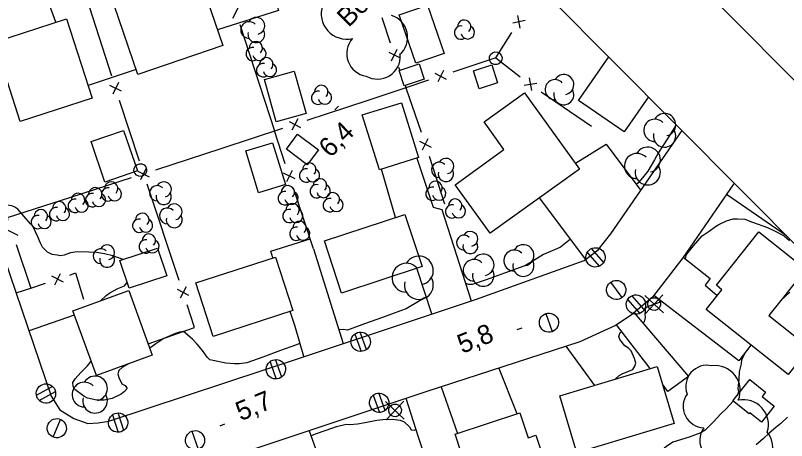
# Model space of a CAD drawing. Extents: x 381879 to 384696, y 5564785 to 5567594.
# Drawn here: x 383956.9 to 384077.4, y 5566512.9 to 5566579.5 of the extents above; entities that cross this region are included whole.
import ezdxf

# ---------------------------------------------------------------- set-up
doc = ezdxf.new("R2010")
doc.units = 0
for name, color, linetype in [('Niveau 19', 7, 'Continuous'), ('Niveau 2', 7, 'Continuous'), ('Niveau 21', 7, 'Continuous'), ('Niveau 3', 7, 'Continuous'), ('Niveau 31', 7, 'Continuous'), ('Niveau 36', 7, 'Continuous'), ('Niveau 37', 7, 'Continuous'), ('Niveau 44', 7, 'Continuous'), ('Niveau 60', 7, 'Continuous')]:
    doc.layers.add(name, color=color, linetype=linetype)

msp = doc.modelspace()

# ---------------------------------------------------------------- linework, layer by layer
at = {"layer": 'Niveau 19'}
for points in [[(383963.19, 5566578.39), (383960.58, 5566585.59)], [(383997.79, 5566580.76), (383997.95, 5566580.25), (383988.45, 5566577.19)], [(383975.72, 5566571.01), (383968.22, 5566568.49)], [(384044.35, 5566556.32), (384049.17, 5566559.34), (384054.58, 5566552.06)], [(384019.57, 5566557.12), (384022.16, 5566549.45), (384023.5, 5566549.11), (384028.1, 5566534.81)], [(384016.26, 5566547.86), (384014.04, 5566555.4)], [(384045.97, 5566541.3), (384038.75, 5566550.93)], [(384077.33, 5566544.99), (384067.96, 5566551.43)], [(383997.09, 5566541.53), (383996.76, 5566542.57), (384002.92, 5566544.51)], [(384003.44, 5566542.93), (384006.66, 5566532.61), (384008.06, 5566528.12)], [(384061.2, 5566541.62), (384065.42, 5566538.28), (384064.66, 5566537.26), (384066.52, 5566535.63)], [(384021.92, 5566532.75), (384019.6, 5566539.91)], [(383956.96, 5566536.05), (383959.41, 5566536.83)], [(384071.78, 5566527.89), (384069.87, 5566525.42), (384056.59, 5566535.63)], [(383966.07, 5566532.59), (383958.99, 5566530.11)], [(384001.95, 5566526.08), (384000.55, 5566530.77), (383999.78, 5566533.15)], [(384053.55, 5566532.95), (384062.05, 5566522.98), (384058.82, 5566520.64), (384057.95, 5566521.77)], [(384056.06, 5566524.21), (384050.78, 5566531.05)], [(384042.88, 5566527.72), (384047.37, 5566521.59)], [(384035.27, 5566517.14), (384032.41, 5566524.31)], [(384023.4, 5566521.37), (384025.96, 5566514.07)], [(384027.82, 5566507.07), (384022.54, 5566505.35), (384019.85, 5566513.5), (384017.91, 5566519.55)], [(384002.75, 5566514.47), (384005.29, 5566507.33)]]:
    msp.add_lwpolyline(points, dxfattribs=at)
at = {"layer": 'Niveau 2'}
for points in [[(383962.63, 5566542.07), (383961.89, 5566542.44), (383961.08, 5566543.22), (383960.76, 5566543.81), (383960.38, 5566544.84), (383959.62, 5566546.4), (383959.24, 5566546.86), (383957.24, 5566549.15), (383956.79, 5566549.45), (383956.29, 5566549.65), (383955.29, 5566549.82), (383953.68, 5566550.21), (383953.28, 5566550.56), (383953.09, 5566551.07), (383952.61, 5566551.98), (383952.14, 5566553.17), (383951.3, 5566555.46), (383950.23, 5566558.39), (383949.32, 5566560.95), (383948.38, 5566563.55), (383947.3, 5566565.69), (383946.95, 5566565.68)], [(384060.11, 5566562.35), (384058.69, 5566560.11), (384057.33, 5566557.99), (384056.72, 5566556.86), (384055.68, 5566555.1), (384054.87, 5566554.04), (384054.13, 5566553.21), (384053.87, 5566553.02)], [(384061.57, 5566541.33), (384061.65, 5566541.97), (384062, 5566542.35), (384062.79, 5566543.4), (384064.16, 5566544.96), (384065.28, 5566545.73), (384066.25, 5566546.45), (384066.78, 5566546.75), (384067.99, 5566547.3), (384069, 5566547.62), (384069.69, 5566547.66), (384070.81, 5566547.56), (384072.01, 5566547.14), (384074.38, 5566546.28), (384075.36, 5566545.81), (384076.97, 5566544.97), (384077.82, 5566544.26)], [(384043.61, 5566544.44), (384042.03, 5566543.19), (384041.45, 5566542.96), (384039.37, 5566542.07), (384038.29, 5566541.36), (384036.55, 5566540.34), (384035.71, 5566540.04), (384033.3, 5566539.16), (384030.41, 5566538.09), (384028.23, 5566537.36), (384027.68, 5566537.35), (384027.22, 5566537.53)], [(383973.71, 5566541.29), (383972.1, 5566541.83), (383970.8, 5566542.17), (383969.55, 5566542.35), (383968.35, 5566542.42), (383966.54, 5566542.47), (383965.47, 5566542.31), (383964.46, 5566541.94), (383963.93, 5566541.86), (383963.39, 5566541.94), (383962.63, 5566542.07)], [(383970.15, 5566534.8), (383971.04, 5566535.66), (383971.62, 5566536.06), (383972.89, 5566536.73), (383973.91, 5566537.15), (383974.34, 5566537.66)], [(384077.87, 5566536.16), (384076.41, 5566534.81)], [(384021.06, 5566535.42), (384020.7, 5566535.25), (384020.12, 5566534.85), (384017.93, 5566533.57), (384017.03, 5566533.24), (384014.21, 5566532.21), (384011.41, 5566531.19), (384008.73, 5566530.24), (384008.12, 5566530.34), (384007.4, 5566530.25)], [(384054.86, 5566531.41), (384055.18, 5566531.55), (384055.32, 5566532.21), (384055.26, 5566532.74), (384055.39, 5566533.79), (384055.95, 5566534.02)], [(384055.95, 5566534.02), (384057.81, 5566534.7)], [(383989.2, 5566525.18), (383987.25, 5566525.57), (383986.85, 5566526.02), (383986.1, 5566527.05), (383985.27, 5566528.02), (383984.54, 5566528.8), (383983.13, 5566529.99), (383982.51, 5566529.93), (383981.86, 5566529.69), (383980.07, 5566528.92), (383978.81, 5566528.07), (383977.85, 5566527.4)], [(384050.55, 5566522.55), (384051.18, 5566523.13), (384051.69, 5566523.38), (384053.33, 5566524.08), (384053.64, 5566524.58), (384053.82, 5566525.07), (384053.58, 5566525.79), (384053.07, 5566527.01), (384052.68, 5566527.38), (384052.06, 5566527.75), (384051.31, 5566528.75), (384051.15, 5566529.23), (384051.34, 5566529.83), (384051.6, 5566529.99)], [(384001.33, 5566528.15), (384000.65, 5566527.89), (383998.28, 5566527.03), (383995.5, 5566526.02), (383993.01, 5566525.13), (383991.82, 5566524.94), (383991.1, 5566524.95), (383989.73, 5566525.07), (383989.2, 5566525.18)], [(384070.93, 5566526.79), (384070.32, 5566525.58), (384070.24, 5566524.98), (384069.96, 5566523.69), (384069.91, 5566522.5), (384069.76, 5566521.1), (384069.83, 5566520.6), (384069.7, 5566520.07)], [(383974.51, 5566524.93), (383973.57, 5566524.38), (383973.02, 5566523.92), (383972.85, 5566523.37), (383973.05, 5566522.83), (383973.51, 5566521.8), (383974.04, 5566521.59), (383974.31, 5566521.12), (383973.92, 5566520.61), (383973.41, 5566520.21), (383971.99, 5566519.55), (383970.71, 5566519.27), (383969.58, 5566519.29), (383968.12, 5566519.59), (383967.57, 5566519.9), (383966.13, 5566520.93), (383965.9, 5566521.42), (383965.86, 5566522.06), (383966.19, 5566522.63), (383967.07, 5566523.61), (383968.14, 5566524.62), (383968.69, 5566525.39)], [(383988.02, 5566525.55), (383988.02, 5566525.55)], [(384069, 5566519.14), (384067.91, 5566517.92), (384067.01, 5566517.08), (384065.94, 5566515.9), (384064.66, 5566514.58), (384063.97, 5566514.18), (384062.95, 5566513.79), (384062.16, 5566513.5)], [(384003.03, 5566513.69), (384003.75, 5566513.99), (384005.4, 5566514.6), (384007.04, 5566515.13), (384008.54, 5566515.5), (384009.1, 5566515.49), (384010.32, 5566515.58), (384011.49, 5566515.77), (384013.35, 5566516.15), (384014.29, 5566516.24), (384015.77, 5566516.28), (384016.97, 5566516.13), (384017.58, 5566515.86), (384018.43, 5566515.1), (384018.68, 5566514.64), (384019.18, 5566514.57), (384019.47, 5566514.68)], [(384077.48, 5566516.59), (384076.46, 5566515.6), (384075.69, 5566515.02), (384074.64, 5566514.13), (384073.74, 5566513.25), (384072.59, 5566512.26)], [(384062.16, 5566513.5), (384059.6, 5566512.68), (384058.57, 5566512.01), (384058.21, 5566511.74)]]:
    msp.add_lwpolyline(points, dxfattribs=at)
at = {"layer": 'Niveau 21'}
for points in [[(383944.6, 5566579.59), (383944.19, 5566578.25), (383943.93, 5566576.52), (383944.16, 5566574.79), (383944.55, 5566572.83), (383954.14, 5566544.31), (383962.47, 5566519.9), (383963.82, 5566517.78), (383965.98, 5566516.39), (383968.16, 5566515.63), (383969.77, 5566515.71), (383971.47, 5566516.01), (384002.02, 5566526.1), (384028.76, 5566535.03), (384045.72, 5566541.11), (384047.93, 5566542.77), (384049.91, 5566545.28), (384061.02, 5566561.43)], [(384069.18, 5566553.2), (384061.14, 5566541.54), (384056.39, 5566535.36), (384053.09, 5566532.56), (384050.62, 5566530.94), (384045.04, 5566528.42), (384021.16, 5566520.64), (383993.82, 5566511.48), (383978.28, 5566506.25), (383975.83, 5566505.42), (383973.59, 5566504.86), (383971.33, 5566504.57), (383968.63, 5566504.67), (383966.03, 5566504.98), (383964.02, 5566505.65), (383961.77, 5566506.45), (383959.56, 5566507.5), (383957.25, 5566509.06), (383955.03, 5566511.77)]]:
    msp.add_lwpolyline(points, dxfattribs=at)
at = {"layer": 'Niveau 3'}
for p, q in [((384006.78, 5566564.69), (384007.35, 5566565.26)), ((384035.28, 5566530.33), (384036.03, 5566530.61)), ((383988.84, 5566515.25), (383989.59, 5566515.55))]:
    msp.add_line(p, q, dxfattribs=at)
at = {"layer": 'Niveau 31'}
for points in [[(383972.3, 5566581.06), (383985.59, 5566585.6), (383989.28, 5566574.77), (383975.99, 5566570.23)], [(384021.27, 5566581.07), (384023.87, 5566573.5), (384019.45, 5566571.98), (384016.85, 5566579.55)], [(383953.59, 5566575.29), (383964.85, 5566578.93), (383968.86, 5566566.52), (383957.59, 5566562.88)], [(384016.81, 5566570.83), (384019.95, 5566571.86), (384020.73, 5566569.47), (384017.59, 5566568.44)], [(384028.42, 5566570.8), (384031.29, 5566571.73), (384032.21, 5566568.9), (384029.34, 5566567.97)], [(384000.43, 5566570.74), (384002.27, 5566564.11), (383997.61, 5566562.82), (383995.77, 5566569.45)], [(384045, 5566555.42), (384031.03, 5566545.38), (384025.56, 5566552.98), (384033.2, 5566558.47), (384030.1, 5566562.79), (384036.43, 5566567.34)], [(384017.19, 5566565.8), (384019.87, 5566557.21), (384013.73, 5566555.3), (384011.05, 5566563.89)], [(383973.75, 5566561.48), (383975.93, 5566555.12), (383970.86, 5566553.38), (383968.68, 5566559.74)], [(384000.96, 5566560.87), (384004.23, 5566558.41), (384002.47, 5566556.07), (383999.2, 5566558.53)], [(383994.87, 5566551.73), (383992.86, 5566558.26), (383997.03, 5566559.54), (383999.04, 5566553.01)], [(384005.14, 5566544.17), (384017.7, 5566548.34), (384020.41, 5566540.18), (384007.84, 5566536.01)], [(384066.39, 5566537.24), (384073.01, 5566545.6), (384080.35, 5566539.78), (384074.58, 5566532.5), (384080.92, 5566527.48), (384077.6, 5566523.28), (384064.78, 5566533.44), (384067.25, 5566536.55)], [(383973.2, 5566541.12), (383979.09, 5566543.05), (383980.51, 5566538.74), (383974.62, 5566536.81)], [(384000.21, 5566533.29), (383987.76, 5566529.24), (383985.03, 5566537.61), (383997.48, 5566541.66)], [(383974.57, 5566536.41), (383978.25, 5566526.29), (383969.52, 5566523.12), (383965.84, 5566533.23)], [(384041.91, 5566519.94), (384057.11, 5566524.53), (384059.81, 5566515.63), (384044.6, 5566511.03)], [(384068.97, 5566519.17), (384071.63, 5566522.48), (384074.08, 5566520.5), (384073.55, 5566519.84), (384075.43, 5566518.32), (384073.44, 5566515.85), (384071.64, 5566517.31), (384071.5, 5566517.12)], [(384038.53, 5566508.72), (384028.38, 5566505.37), (384025.55, 5566513.93), (384035.7, 5566517.28), (384036.99, 5566513.38), (384038.17, 5566513.78), (384039.46, 5566509.87), (384038.26, 5566509.46)]]:
    msp.add_lwpolyline(points, close=True, dxfattribs=at)
msp.add_lwpolyline([(384055.78, 5566566.71), (384051.98, 5566561.23), (384044.87, 5566566.17), (384049.58, 5566572.96)], dxfattribs=at)
at = {"layer": 'Niveau 36'}
for p, q in [((384046.2, 5566542.39), (384048.1, 5566540.2)), ((384048.78, 5566540.81), (384046.88, 5566543)), ((384049.83, 5566537.73), (384051.61, 5566535.31)), ((384052.52, 5566535.02), (384054.44, 5566532.84)), ((384055.12, 5566533.46), (384053.2, 5566535.64)), ((384055.19, 5566535.66), (384058.11, 5566532.94)), ((384055.29, 5566532.84), (384058.01, 5566535.76)), ((384039.72, 5566532.81), (384040.74, 5566529.99)), ((384009.89, 5566529.6), (384010.87, 5566526.87)), ((384011.73, 5566527.2), (384010.75, 5566529.93)), ((383998.47, 5566522.89), (383997.51, 5566525.62)), ((383996.65, 5566525.29), (383997.61, 5566522.56)), ((383962.66, 5566521.41), (383960.13, 5566520)), ((383960.6, 5566519.21), (383963.13, 5566520.62)), ((384012.77, 5566520.06), (384013.77, 5566517.34)), ((384014.63, 5566517.68), (384013.63, 5566520.4)), ((384014.71, 5566519.04), (384017.63, 5566516.32)), ((384014.81, 5566516.22), (384017.53, 5566519.14)), ((383972.04, 5566516.98), (383972.91, 5566514.22)), ((383973.78, 5566514.52), (383972.91, 5566517.28)), ((383962.74, 5566513.49), (383963.92, 5566516.25)), ((383984.43, 5566514.43), (383985.43, 5566511.61))]:
    msp.add_line(p, q, dxfattribs=at)
for centre, major_axis in [((384031.92, 5566572.75), (0.799, -0.602)), ((383976.37, 5566555.27), (0.799, -0.602)), ((384047.49, 5566541.61), (-1.21, 0.91)), ((384050.73, 5566536.51), (1.2, -0.9)), ((384053.82, 5566534.23), (1.21, -0.91)), ((384056.66, 5566534.3), (0.799, -0.602)), ((384040.23, 5566531.39), (1.2, -0.9)), ((384010.81, 5566528.41), (-1.21, 0.91)), ((383997.56, 5566524.1), (-1.21, 0.91)), ((383961.64, 5566520.31), (-1.21, 0.91)), ((384013.7, 5566518.86), (1.21, -0.91)), ((384016.18, 5566517.68), (0.799, -0.602)), ((383972.91, 5566515.76), (-1.21, 0.91)), ((383963.33, 5566514.88), (-1.2, 0.9)), ((383984.93, 5566513.01), (1.2, -0.9))]:
    msp.add_ellipse(centre, major_axis=major_axis, ratio=0.999875, dxfattribs=at)
at = {"layer": 'Niveau 37'}
for p, q in [((383971.92, 5566569.96), (383967.05, 5566585.07)), ((383990.85, 5566579.05), (383991.76, 5566580.84)), ((384014.13, 5566579.11), (384015.44, 5566575.16)), ((384036.53, 5566578.65), (384034.56, 5566578.23)), ((384035.75, 5566577.46), (384035.34, 5566579.42)), ((383991.93, 5566578.04), (383997.33, 5566561.4)), ((384031.92, 5566572.82), (384034.45, 5566576.77)), ((384015.19, 5566573.71), (384016.99, 5566572.82)), ((384015.65, 5566572.36), (384016.53, 5566574.17)), ((384031.92, 5566572.82), (384025.19, 5566570.6)), ((384031.92, 5566572.82), (384035.74, 5566569.86)), ((384022.39, 5566570.41), (384024.19, 5566569.51)), ((384023.74, 5566570.86), (384022.85, 5566569.06)), ((383972.99, 5566568.95), (383972.08, 5566567.16)), ((384036.37, 5566568.54), (384038.35, 5566568.86)), ((384037.53, 5566567.71), (384037.2, 5566569.69)), ((383973.43, 5566567.6), (383971.64, 5566568.51)), ((384017.89, 5566568.14), (384020.28, 5566561.22)), ((384038.99, 5566567.53), (384046.9, 5566562.12)), ((383976.24, 5566556.64), (383973.15, 5566566.15)), ((384011.92, 5566566.14), (384002.42, 5566563.02)), ((383999.62, 5566562.85), (384001.42, 5566561.94)), ((384000.97, 5566563.29), (384000.07, 5566561.5)), ((383998.62, 5566561.77), (383989.12, 5566558.65)), ((383999.03, 5566556.22), (383997.33, 5566561.4)), ((384020.01, 5566559.77), (384021.81, 5566558.87)), ((384020.46, 5566558.42), (384021.36, 5566560.22)), ((383989.12, 5566558.65), (383978.77, 5566555.27)), ((384021.53, 5566557.42), (384023.92, 5566549.99)), ((383977.32, 5566555.54), (383976.41, 5566553.75)), ((383975.97, 5566555.11), (383977.76, 5566554.19)), ((384000.56, 5566553.87), (383998.77, 5566554.77)), ((384000.11, 5566555.22), (383999.21, 5566553.42)), ((383974.96, 5566554.03), (383965.45, 5566550.95)), ((383982.46, 5566538.01), (383977.45, 5566553.08)), ((384003.44, 5566542.93), (384000.29, 5566552.42)), ((383955.45, 5566545.96), (383957.25, 5566545.08)), ((383957, 5566543.63), (383959.26, 5566536.79)), ((383964.36, 5566537.75), (383962.56, 5566538.65)), ((383963.01, 5566537.3), (383963.91, 5566539.1)), ((383959.26, 5566536.79), (383961.56, 5566537.57)), ((383983.97, 5566535.65), (383982.18, 5566536.56)), ((383983.53, 5566537), (383982.63, 5566535.21))]:
    msp.add_line(p, q, dxfattribs=at)
for points in [[(384016.74, 5566571.37), (384016.92, 5566570.87)], [(384021.4, 5566569.32), (384017.89, 5566568.14), (384011.92, 5566566.14)], [(384017.76, 5566568.5), (384017.89, 5566568.14)], [(383965.45, 5566550.95), (383955.56, 5566547.77), (383955.7, 5566547.41)], [(383965.35, 5566538.84), (383966.24, 5566539.18), (383967.5, 5566535.09)], [(383977.6, 5566528.08), (383984.83, 5566530.63), (383983.7, 5566534.2)]]:
    msp.add_lwpolyline(points, dxfattribs=at)
at = {"layer": 'Niveau 44'}
for centre, radius, start, end in [((384008.63, 5566579.73), 3.98, 161.0374, 283.0227), ((383993.38, 5566577.17), 1.31, 44.1153, 269.8039), ((383994.51, 5566577.83), 1.31, 282.2692, 149.7262), ((384014.6, 5566576.05), 3.55, 310.0737, 73.5461), ((383994.51, 5566576.51), 1.31, 166.9368, 29.6212), ((384012.18, 5566573.49), 3.55, 138.2965, 261.9359), ((384013.46, 5566573.05), 3.55, 239.9756, 3.4915), ((384042.54, 5566568.63), 1.57, 282.2692, 149.7262), ((384041.19, 5566567.84), 1.57, 44.1153, 269.8039), ((384042.54, 5566567.05), 1.57, 166.9368, 29.6212), ((384058.29, 5566562.36), 1.75, 282.2692, 149.7262), ((384056.79, 5566561.48), 1.75, 44.1153, 269.8039), ((384058.29, 5566560.6), 1.75, 166.9368, 29.6212), ((384053.98, 5566555.9), 1.97, 44.1153, 269.8039), ((384055.67, 5566556.89), 1.97, 282.2692, 149.7262), ((384024.14, 5566555.89), 1.21, 282.2692, 149.7262), ((384023.1, 5566555.29), 1.21, 44.1153, 269.8039), ((384055.67, 5566554.91), 1.97, 166.9368, 29.6212), ((384024.14, 5566554.68), 1.21, 166.9368, 29.6212), ((383980.04, 5566552.24), 1.19, 282.2692, 149.7262), ((383979.02, 5566551.65), 1.19, 44.1153, 269.8039), ((383980.04, 5566551.05), 1.19, 166.9368, 29.6212), ((383981.68, 5566548.72), 1.24, 282.2692, 149.7262), ((383980.62, 5566548.1), 1.24, 44.1153, 269.8039), ((383981.68, 5566547.48), 1.24, 166.9368, 29.6212), ((384026.95, 5566543.92), 1.16, 44.1153, 269.8039), ((384027.95, 5566544.51), 1.16, 282.2692, 149.7262), ((383971.19, 5566542.39), 1.16, 282.2692, 149.7262), ((384027.95, 5566543.34), 1.16, 166.9368, 29.6212), ((384036.24, 5566541.94), 1.65, 282.2692, 149.7262), ((383970.19, 5566541.8), 1.16, 44.1153, 269.8039), ((384034.82, 5566541.11), 1.65, 44.1153, 269.8039), ((383971.19, 5566541.22), 1.16, 166.9368, 29.6212), ((384019.9, 5566539.55), 2.26, 282.2692, 149.7262), ((384028.52, 5566539.6), 1.68, 44.1153, 269.8039), ((384029.97, 5566540.44), 1.68, 282.2692, 149.7262), ((384036.24, 5566540.29), 1.65, 166.9368, 29.6212), ((384017.96, 5566538.42), 2.26, 44.1153, 269.8039), ((384029.97, 5566538.76), 1.68, 166.9368, 29.6212), ((384019.9, 5566537.29), 2.26, 166.9368, 29.6212), ((383969.31, 5566521.11), 1.93, 282.2692, 149.7262), ((383967.64, 5566520.15), 1.93, 44.1153, 269.8039), ((383969.31, 5566519.18), 1.93, 166.9368, 29.6212)]:
    msp.add_arc(centre, radius, start, end, dxfattribs=at)
for centre, major_axis, ratio, start_param, end_param in [((384026.98, 5566577.69), (0.836, -0.629), 0.999875, 6.162675, 10.101684), ((384026.49, 5566576.77), (0.836, -0.629), 0.999875, 2.023129, 5.909704), ((384027.54, 5566576.81), (0.836, -0.629), 0.999875, 4.036058, 8.005933), ((383994.42, 5566574.34), (0.836, -0.629), 0.999875, 6.162675, 10.101684), ((383993.93, 5566573.42), (0.836, -0.629), 0.999875, 2.023129, 5.909704), ((383994.98, 5566573.46), (0.836, -0.629), 0.999875, 4.036058, 8.005933), ((383996.07, 5566571.81), (0.836, -0.629), 0.999875, 6.162675, 10.101684), ((383995.58, 5566570.89), (0.836, -0.629), 0.999875, 2.023129, 5.909704), ((383996.63, 5566570.93), (0.836, -0.629), 0.999875, 4.036058, 8.005933), ((384004.17, 5566566.57), (0.836, -0.629), 0.999875, 2.023129, 5.909704), ((384004.66, 5566567.49), (0.836, -0.629), 0.999875, 6.162675, 10.101684), ((384005.22, 5566566.61), (0.836, -0.629), 0.999875, 4.036058, 8.005933), ((384002.3, 5566554.41), (0.836, -0.629), 0.999875, 2.023129, 5.909704), ((384002.79, 5566555.33), (0.836, -0.629), 0.999875, 6.162675, 10.101684), ((384003.35, 5566554.45), (0.836, -0.629), 0.999875, 4.036058, 8.005933), ((383971.83, 5566552.38), (0.836, -0.629), 0.999875, 6.162675, 10.101684), ((384003.96, 5566551.95), (0.836, -0.629), 0.999875, 2.023129, 5.909704), ((384004.45, 5566552.87), (0.836, -0.629), 0.999875, 6.162675, 10.101684), ((384022.51, 5566552.48), (0.836, -0.629), 0.999875, 6.162675, 10.101684), ((383969.35, 5566551.48), (0.836, -0.629), 0.999875, 6.162675, 10.101684), ((383971.34, 5566551.46), (0.836, -0.629), 0.999875, 2.023129, 5.909704), ((383972.39, 5566551.5), (0.836, -0.629), 0.999875, 4.036058, 8.005933), ((383998.94, 5566550.87), (0.836, -0.629), 0.999875, 2.023129, 5.909704), ((383999.43, 5566551.79), (0.836, -0.629), 0.999875, 6.162675, 10.101684), ((383999.99, 5566550.91), (0.836, -0.629), 0.999875, 4.036058, 8.005933), ((384005.01, 5566551.99), (0.836, -0.629), 0.999875, 4.036058, 8.005933), ((384006.47, 5566550.69), (0.836, -0.629), 0.999875, 6.162675, 10.101684), ((384022.02, 5566551.56), (0.836, -0.629), 0.999875, 2.023129, 5.909704), ((384023.07, 5566551.6), (0.836, -0.629), 0.999875, 4.036058, 8.005933), ((383966.16, 5566549.67), (0.836, -0.629), 0.999875, 2.023129, 5.909704), ((383966.65, 5566550.59), (0.836, -0.629), 0.999875, 6.162675, 10.101684), ((383967.21, 5566549.71), (0.836, -0.629), 0.999875, 4.036058, 8.005933), ((383968.86, 5566550.56), (0.836, -0.629), 0.999875, 2.023129, 5.909704), ((383969.91, 5566550.6), (0.836, -0.629), 0.999875, 4.036058, 8.005933), ((384005.98, 5566549.77), (0.836, -0.629), 0.999875, 2.023129, 5.909704), ((384007.03, 5566549.81), (0.836, -0.629), 0.999875, 4.036058, 8.005933), ((384025.58, 5566549.71), (0.836, -0.629), 0.999875, 6.162675, 10.101684), ((383963.23, 5566548.36), (0.836, -0.629), 0.999875, 2.023129, 5.909704), ((383963.72, 5566549.28), (0.836, -0.629), 0.999875, 6.162675, 10.101684), ((384000.17, 5566549), (0.836, -0.629), 0.999875, 6.162675, 10.101684), ((384025.09, 5566548.79), (0.836, -0.629), 0.999875, 2.023129, 5.909704), ((384026.14, 5566548.83), (0.836, -0.629), 0.999875, 4.036058, 8.005933), ((383960.36, 5566547.13), (0.836, -0.629), 0.999875, 2.023129, 5.909704), ((383960.85, 5566548.05), (0.836, -0.629), 0.999875, 6.162675, 10.101684), ((383964.28, 5566548.4), (0.836, -0.629), 0.999875, 4.036058, 8.005933), ((383976.7, 5566547.48), (0.836, -0.629), 0.999875, 6.162675, 10.101684), ((383999.68, 5566548.08), (0.836, -0.629), 0.999875, 2.023129, 5.909704), ((384000.73, 5566548.12), (0.836, -0.629), 0.999875, 4.036058, 8.005933), ((383961.41, 5566547.17), (0.836, -0.629), 0.999875, 4.036058, 8.005933), ((383976.21, 5566546.56), (0.836, -0.629), 0.999875, 2.023129, 5.909704), ((383977.26, 5566546.6), (0.836, -0.629), 0.999875, 4.036058, 8.005933), ((384001.25, 5566546.22), (0.836, -0.629), 0.999875, 6.162675, 10.101684), ((384000.76, 5566545.3), (0.836, -0.629), 0.999875, 2.023129, 5.909704), ((384001.81, 5566545.34), (0.836, -0.629), 0.999875, 4.036058, 8.005933), ((383977.71, 5566544.23), (0.836, -0.629), 0.999875, 6.162675, 10.101684), ((383977.22, 5566543.31), (0.836, -0.629), 0.999875, 2.023129, 5.909704), ((383978.27, 5566543.35), (0.836, -0.629), 0.999875, 4.036058, 8.005933), ((384064.93, 5566521.4), (-3.09, -1.24), 0.9993, 4.105138, 6.263653), ((384066.23, 5566520.79), (-2.02, 3.34), 0.991918, 3.764403, 5.880879), ((384064.54, 5566518.3), (1.49, -2.99), 0.999984, 3.636623, 5.788155), ((384070.65, 5566515.47), (-2.7, 2.8), 0.991991, 3.63176, 5.736372), ((384067.14, 5566512.99), (1.44, -3.02), 0.999984, 3.63548, 4.829298), ((384071.33, 5566511.81), (2.55, -2.95), 0.994197, 5.671741, 7.825502)]:
    msp.add_ellipse(centre, major_axis=major_axis, ratio=ratio, start_param=start_param, end_param=end_param, dxfattribs=at)
at = {"layer": 'Niveau 60'}
for points in [[(383794.43, 5567565.69), (383439.46, 5567213.56), (384312.69, 5566333.28), (384667.66, 5566685.41)], [(383653.8, 5566971.92), (383426.67, 5567200.87), (383197.47, 5566973.49), (381907.4, 5565693.71), (382780.65, 5564813.45), (384299.92, 5566320.61)]]:
    msp.add_lwpolyline(points, close=True, dxfattribs=at)

# ---------------------------------------------------------------- texts
at = {"layer": 'Niveau 3'}
for s, rotation, p in [('6,4', 44.7717, (384006.06, 5566557.07)), ('5,8', 21.751, (384026.66, 5566526.5)), ('5,7', 22.5615, (383992.06, 5566515.96))]:
    msp.add_text(s, height=3, rotation=rotation, dxfattribs=at).set_placement(p)
at = {"layer": 'Niveau 44'}
msp.add_text('Bois', height=3, rotation=44.7707, dxfattribs=at).set_placement((384008.92, 5566577.48))

doc.saveas('drawing.dxf')
